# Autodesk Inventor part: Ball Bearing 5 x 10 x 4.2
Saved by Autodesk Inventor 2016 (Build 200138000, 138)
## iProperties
Created: 2016-03
Part Number: Ball Bearing 5 x 10 x 4.2
Material: Generic
Document SubType Name: Modeling
Designer: bongo_000
Density: 1 g/cm^3
Appearance: Default
Author: bongo_000
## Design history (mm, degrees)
feature "REVOLVE1"
body "Solid1"
